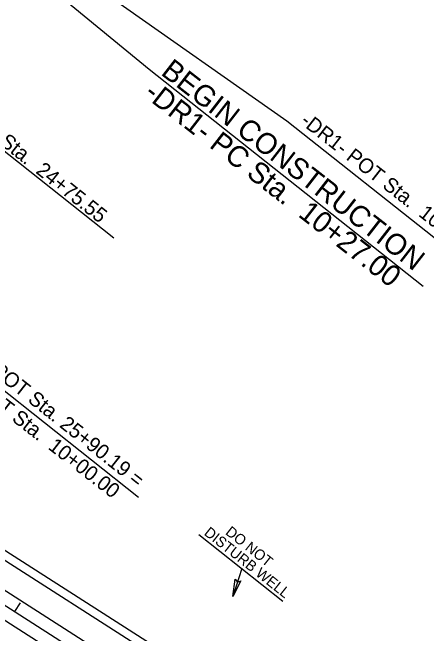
# Model space of a CAD drawing. Extents: x 1778969 to 1790720, y 807089 to 817794.
# Drawn here: x 1782840.8 to 1783037.6, y 814148.6 to 814443.8 of the extents above; entities that cross this region are included whole.
import ezdxf

# ---------------------------------------------------------------- set-up
doc = ezdxf.new("R2010")
doc.units = 0
for name, color, linetype in [('Prop DSN Text', 7, 'Continuous'), ('Prop EOT', 7, 'Continuous'), ('Prop Horizontal Alignment', 7, 'Continuous'), ('Prop Horizontal Alignment Station Label', 7, 'Continuous'), ('Prop Horizontal Alignment Tick Small', 7, 'Continuous'), ('Prop Lane Lines', 7, 'Continuous'), ('Prop Paved Shoulder', 7, 'Continuous'), ('Prop Terminator CELL', 7, 'Continuous')]:
    doc.layers.add(name, color=color, linetype=linetype)

msp = doc.modelspace()

# ---------------------------------------------------------------- linework, layer by layer
at = {"layer": 'Prop DSN Text'}
for p, q in [((1782929.35, 814195.65), (1782969.35, 814163.99)), ((1782949.79, 814179.47), (1782945.63, 814166.29))]:
    msp.add_line(p, q, dxfattribs=at)
at = {"layer": 'Prop EOT'}
msp.add_line((1782662.57, 814295.14), (1783159.17, 813977.59), dxfattribs=at)
at = {"layer": 'Prop Horizontal Alignment'}
msp.add_line((1782652.87, 814279.97), (1783782.01, 813557.97), dxfattribs=at)
msp.add_arc((1780718.82, 815764.26), 2330, 324.08998, 342.60824, dxfattribs=at)
at = {"layer": 'Prop Horizontal Alignment Station Label'}
for p, q in [((1782819.56, 814487.81), (1782905.82, 814416.85)), ((1782846.81, 814479.76), (1782971.22, 814392.32)), ((1782905.82, 814416.85), (1783036.01, 814313.78)), ((1782806.02, 814402.42), (1782889.07, 814336.67)), ((1782971.22, 814392.32), (1783067.79, 814315.86)), ((1782809.85, 814285.43), (1782900.77, 814213.44))]:
    msp.add_line(p, q, dxfattribs=at)
at = {"layer": 'Prop Horizontal Alignment Tick Small'}
msp.add_line((1782841.96, 814159.06), (1782844.66, 814163.27), dxfattribs=at)
at = {"layer": 'Prop Lane Lines'}
for p, q in [((1782656.1, 814285.03), (1783144.28, 813972.87)), ((1782649.64, 814274.92), (1783146.07, 813957.48))]:
    msp.add_line(p, q, dxfattribs=at)
at = {"layer": 'Prop Paved Shoulder'}
msp.add_line((1782664.72, 814298.51), (1783161.32, 813980.96), dxfattribs=at)
at = {"layer": 'Prop Terminator CELL'}
msp.add_lwpolyline([(1782949.4, 814173.6), (1782945.63, 814166.29), (1782946.71, 814174.49), (1782947.77, 814173.07)], close=True, dxfattribs=at)

# ---------------------------------------------------------------- texts
at = {"layer": 'Prop DSN Text'}
for s, p in [('DISTURB WELL', (1782931.52, 814195.81)), ('DO NOT', (1782941.67, 814196.13))]:
    msp.add_text(s, height=5, rotation=321.6309, dxfattribs=at).set_placement(p)
at = {"layer": 'Prop Horizontal Alignment Station Label'}
for s, height, rotation, p in [('BEGIN CONSTRUCTION', 10, 322.1266, (1782910.89, 814414.54)), ('-DR1- PC Sta.  10+27.00', 10, 322.1266, (1782902.84, 814404.2)), ('-Y1- PT Sta.  24+75.55', 7, 321.5598, (1782807.09, 814403.05)), ('-DR1- POT Sta.  10+00.00', 7, 321.9852, (1782977.27, 814391.26)), ('-Y1- POT Sta. 25+90.19 =', 7, 321.6309, (1782814.65, 814285.21)), ('-Y4- POT Sta.  10+00.00', 7, 322.1355, (1782806.85, 814275.91))]:
    msp.add_text(s, height=height, rotation=rotation, dxfattribs=at).set_placement(p)

doc.saveas('drawing.dxf')
